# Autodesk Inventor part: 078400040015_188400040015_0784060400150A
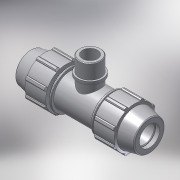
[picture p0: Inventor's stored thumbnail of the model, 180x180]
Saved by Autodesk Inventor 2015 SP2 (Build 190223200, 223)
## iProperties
Created: 2017-02
Part Number: 078400040015_188400040015_0784060400150A
Material: PVC-Piping
Description: PLASSON TEE WITH THREADED MALE OFFTAKE 40-1.1/2"-40
Document SubType Name: Modeling
Designer: KIM
Mass: 92.6774 g
Surface Area: 199.44 cm^2
Volume: 66.1981 cm^3
Density: 1.4 g/cm^3
Appearance: Smooth - White
Author: Кирилл
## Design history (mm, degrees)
derived "07840.ipt"
feature "Solid1::07840.ipt"
feature "Solid2::07840.ipt"
tag "TaggingFeature1"
body "Solid1"
body "Solid2"
other parameters: "d4" = 8.54167, "d5" = 24.6, "d7" = 82, "d11" = 3.41667, "d13" = 120 deg, "d15" = 12 deg, "d16" = 71.34, "d18" = 2, "d19" = 35 deg, "d20" = 17.5 deg, "d21" = 76.26, "d23" = 0, "d25" = 360 deg, "d27" = 1.64, "d33" = 0.8, "d42" = 36.9, "d43" = 2.46, "d46" = 1.2, "d68" = 3.41667, "d72" = 71, "d73" = 47.803, "d74" = 22, "d75" = 54.97345, "d76" = 33.4621, "d77" = 26.4, "d80" = 1.43409, "d91" = 61.5, "d93" = 84, "d95" = 36, "d99" = 205, "d101" = 0, "d103" = 0, "d105" = 0, "E_" = 82, "A_" = 71, "l_" = 84, "l_2" = 22, "H_" = 205, "R_" = 47.803
